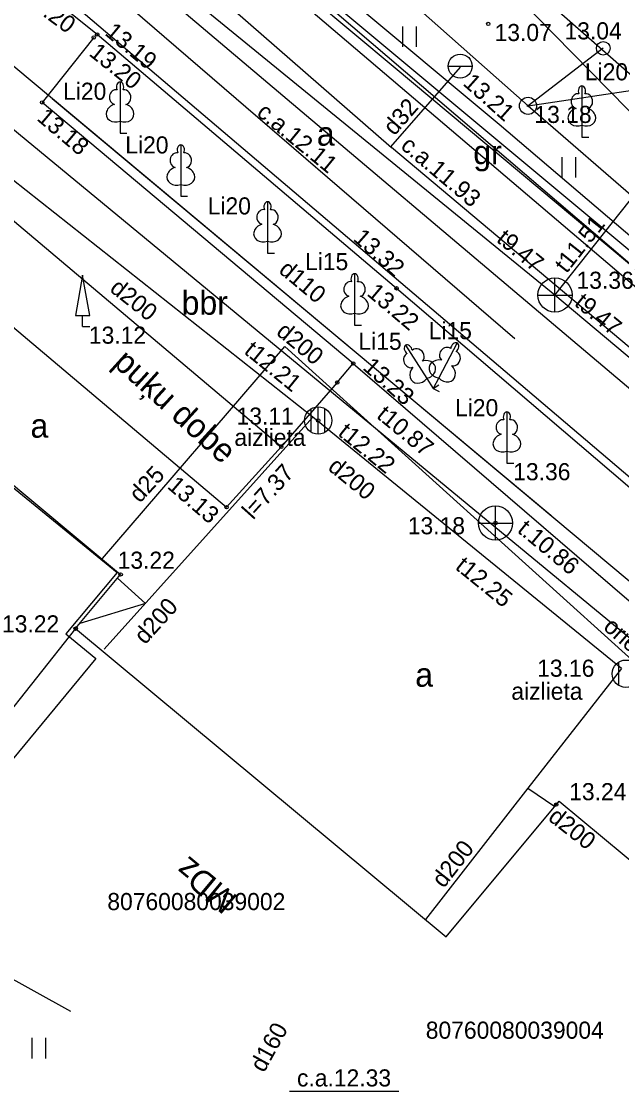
# Model space of a CAD drawing. Extents: x 503877 to 504025, y 304562 to 304725.
# Drawn here: x 503957.69 to 503975.24, y 304562.03 to 304593.32 of the extents above; entities that cross this region are included whole.
import ezdxf

# ---------------------------------------------------------------- set-up
doc = ezdxf.new("R2010")
doc.units = 0
for name, color, linetype in [('20', 7, 'Continuous'), ('25', 7, 'Continuous'), ('41', 7, 'Continuous'), ('42', 7, 'Continuous'), ('APGS_ACRL_####_####_#', 7, 'Continuous'), ('APGS_ACRL_####_TKST_#', 7, 'Continuous'), ('APGS_VADP_ZSPR_####_#', 7, 'Continuous'), ('BUVE_EKAS_####_####_#', 7, 'Continuous'), ('BUVE_EKAS_ADRS_TKST_#', 7, 'Continuous'), ('CELI_CAPM_####_####_#', 7, 'Continuous'), ('CELI_CMAL_####_####_#', 7, 'Continuous'), ('CELI_CSEG_####_TKST_#', 7, 'Continuous'), ('CELI_TAKA_####_####_#', 7, 'Continuous'), ('ELEK_ELEM_####_####_#', 7, 'Continuous'), ('ELEK_STUT_####_####_#', 7, 'Continuous'), ('ELEK_VADV_ZSPR_####_#', 7, 'Continuous'), ('GAZE_VADP_VSP2_####_#', 7, 'Continuous'), ('Level 46', 7, 'Continuous'), ('LKAN_ELEM_####_####_#', 7, 'Continuous'), ('LKAN_ELEM_PAST_TKST_#', 7, 'Continuous'), ('LKAN_VADP_PAST_####_#', 7, 'Continuous'), ('LKAN_VADP_PAST_TKST_#', 7, 'Continuous'), ('RELJ_AATZ_####_TKST_#', 7, 'Continuous'), ('RELJ_ELEM_####_####_#', 7, 'Continuous'), ('SAKK_KKAN_####_####_#', 7, 'Continuous'), ('SAKT_VADP_KABE_####_#', 7, 'Continuous'), ('SAKT_VADP_NEDR_####_#', 7, 'Continuous'), ('SKAN_DETP_PAST_####_#', 7, 'Continuous'), ('SKAN_ELEM_####_####_#', 7, 'Continuous'), ('SKAN_ELEM_PAST_TKST_#', 7, 'Continuous'), ('SKAN_VADP_PAST_####_#', 7, 'Continuous'), ('SKAN_VADP_PAST_####_I', 7, 'Continuous'), ('SKAN_VADP_PAST_TKST_#', 7, 'Continuous'), ('SKAN_VADP_PAST_TKST_I', 7, 'Continuous'), ('SKAN_VADP_SPDK_TKST_I', 7, 'Continuous'), ('TERT_DIAM_####_TKST_#', 7, 'Continuous'), ('TERT_ELEM_####_####_#', 7, 'Continuous'), ('TERT_IZMT_####_TKST_#', 7, 'Continuous'), ('UDTK_ELEM_####_####_#', 7, 'Continuous'), ('UDTK_ELEM_####_TKST_#', 7, 'Continuous'), ('UDTK_VADP_NEDR_####_#', 7, 'Continuous'), ('UDTK_VADP_NEDR_TKST_#', 7, 'Continuous'), ('UDTK_VADP_UDEN_####_I', 7, 'Continuous'), ('UDTK_VADP_UDEN_TKST_I', 7, 'Continuous')]:
    doc.layers.add(name, color=color, linetype=linetype)

msp = doc.modelspace()

# ---------------------------------------------------------------- linework, layer by layer
at = {"layer": '20'}
msp.add_line((503960.823, 304605.633), (503983.332, 304582.665), dxfattribs=at)
at = {"layer": '25'}
msp.add_line((503924.947, 304625.297), (503985.325, 304574.255), dxfattribs=at)
at = {"layer": '42'}
msp.add_lwpolyline([(503940.294, 304598.947), (503951.661, 304589.773), (503949.864, 304587.645), (503954.733, 304583.621), (503953.927, 304582.557), (503960.49, 304577.208), (503958.987, 304575.41), (503959.865, 304574.697), (503955.838, 304569.828), (503955.063, 304570.502), (503953.67, 304568.891), (503946.74, 304574.542), (503947.217, 304575.092), (503942.561, 304578.835), (503942.084, 304578.358), (503930.754, 304587.457), (503939.344, 304597.708)], close=True, dxfattribs=at)
at = {"layer": 'APGS_ACRL_####_####_#'}
msp.add_line((503958.587, 304591.069), (503973.167, 304578.886), dxfattribs=at)
at = {"layer": 'APGS_VADP_ZSPR_####_#'}
msp.add_line((503955.752, 304593.437), (503977.746, 304575.06), dxfattribs=at)
at = {"layer": 'BUVE_EKAS_####_####_#'}
for p, q in [((503954.167, 304582.49), (503960.588, 304577.15)), ((503959.271, 304575.566), (503960.588, 304577.15)), ((503959.271, 304575.566), (503955.082, 304570.298)), ((503959.271, 304575.566), (503970.108, 304566.552)), ((503970.108, 304566.552), (503973.411, 304570.524)), ((503973.411, 304570.524), (503979.555, 304565.414))]:
    msp.add_line(p, q, dxfattribs=at)
at = {"layer": 'CELI_CAPM_####_####_#'}
for p, q in [((503968.656, 304585.514), (503959.9, 304592.938)), ((503982.4, 304573.765), (503968.656, 304585.514))]:
    msp.add_line(p, q, dxfattribs=at)
at = {"layer": 'CELI_CMAL_####_####_#'}
for p, q in [((503982.055, 304580.09), (503962.594, 304596.657)), ((503959.9, 304592.938), (503957.88, 304594.554)), ((503959.802, 304592.849), (503958.292, 304590.951)), ((503967.389, 304583.318), (503958.292, 304590.951)), ((503965.285, 304580.881), (503956.281, 304588.468)), ((503954.789, 304586.616), (503963.685, 304579.115)), ((503966.922, 304582.761), (503967.389, 304583.318)), ((503967.389, 304583.318), (503981.868, 304570.859)), ((503966.922, 304582.761), (503965.285, 304580.881)), ((503963.685, 304579.115), (503965.285, 304580.881))]:
    msp.add_line(p, q, dxfattribs=at)
at = {"layer": 'CELI_TAKA_####_####_#'}
msp.add_line((503962.913, 304596.977), (503982.372, 304580.35), dxfattribs=at)
at = {"layer": 'ELEK_ELEM_####_####_#'}
for centre, radius in [((503974.701, 304592.532), 0.2), ((503972.501, 304590.85), 0.25), ((503972.501, 304590.85), 0.0225)]:
    msp.add_circle(centre, radius, dxfattribs=at)
at = {"layer": 'ELEK_STUT_####_####_#'}
msp.add_line((503974.701, 304592.532), (503972.501, 304590.85), dxfattribs=at)
at = {"layer": 'ELEK_VADV_ZSPR_####_#'}
for p, q in [((503938.2, 304621.309), (503972.501, 304590.85)), ((503972.501, 304590.85), (503977.734, 304591.644)), ((503972.501, 304590.85), (504000, 304566.991))]:
    msp.add_line(p, q, dxfattribs=at)
at = {"layer": 'GAZE_VADP_VSP2_####_#'}
for p, q in [((503958.172, 304594.706), (503971.829, 304583.093)), ((503971.829, 304583.093), (503992.301, 304565.684))]:
    msp.add_line(p, q, dxfattribs=at)
at = {"layer": 'Level 46'}
msp.add_line((503943.333, 304620.019), (504006.701, 304564.361), dxfattribs=at)
at = {"layer": 'LKAN_ELEM_####_####_#'}
for p, q in [((503966.363, 304581.251), (503966.363, 304582.051)), ((503966.163, 304581.305), (503966.163, 304581.997)), ((503966.563, 304581.305), (503966.563, 304581.997)), ((503975.16, 304573.902), (503975.16, 304574.594))]:
    msp.add_line(p, q, dxfattribs=at)
for centre in [(503966.363, 304581.651), (503975.36, 304574.248)]:
    msp.add_circle(centre, 0.4, dxfattribs=at)
at = {"layer": 'LKAN_VADP_PAST_####_#'}
for p, q in [((503966.208, 304581.751), (503953.386, 304591.874)), ((503966.208, 304581.751), (503960.104, 304574.963)), ((503975.237, 304574.404), (503966.208, 304581.751)), ((503961.31, 304576.305), (503960.495, 304577.038)), ((503961.31, 304576.305), (503959.391, 304575.711)), ((503975.237, 304574.404), (503972.499, 304570.901)), ((503972.499, 304570.901), (503969.498, 304567.06)), ((503972.499, 304570.901), (503973.281, 304570.367))]:
    msp.add_line(p, q, dxfattribs=at)
at = {"layer": 'RELJ_ELEM_####_####_#'}
for centre in [(503959.9, 304592.938), (503971.337, 304593.245), (503959.802, 304592.849), (503958.292, 304590.951), (503968.656, 304585.514), (503967.389, 304583.318), (503966.922, 304582.761), (503966.363, 304581.651), (503965.285, 304580.881), (503963.685, 304579.115), (503971.549, 304578.653), (503960.588, 304577.15), (503959.271, 304575.566), (503973.326, 304570.421)]:
    msp.add_circle(centre, 0.05, dxfattribs=at)
at = {"layer": 'SAKK_KKAN_####_####_#'}
for p, q in [((503968.613, 304591.954), (503945.607, 304611.208)), ((503986.057, 304577.347), (503968.613, 304591.954))]:
    msp.add_line(p, q, dxfattribs=at)
at = {"layer": 'SAKT_VADP_KABE_####_#'}
for p, q in [((503971.653, 304590.306), (503940.354, 304616.433)), ((503991.251, 304573.616), (503971.653, 304590.306)), ((503959.129, 304564.37), (503952.415, 304568.091))]:
    msp.add_line(p, q, dxfattribs=at)
at = {"layer": 'SAKT_VADP_NEDR_####_#'}
msp.add_line((503997.217, 304568.475), (503924.507, 304629.123), dxfattribs=at)
at = {"layer": 'SKAN_DETP_PAST_####_#'}
msp.add_line((503968.726, 304562.03), (503965.529, 304562.03), dxfattribs=at)
at = {"layer": 'SKAN_ELEM_####_####_#'}
for p, q in [((503973.287, 304584.819), (503973.287, 304585.819)), ((503972.787, 304585.319), (503973.787, 304585.319)), ((503971.549, 304578.153), (503971.549, 304579.153)), ((503971.049, 304578.653), (503972.049, 304578.653))]:
    msp.add_line(p, q, dxfattribs=at)
for centre in [(503973.287, 304585.319), (503971.549, 304578.653)]:
    msp.add_circle(centre, 0.5, dxfattribs=at)
at = {"layer": 'SKAN_VADP_PAST_####_#'}
for p, q in [((503971.339, 304578.696), (503938.881, 304605.476)), ((503984.286, 304568.011), (503971.339, 304578.696))]:
    msp.add_line(p, q, dxfattribs=at)
at = {"layer": 'SKAN_VADP_PAST_####_I'}
for p, q in [((503973.287, 304585.319), (503945.224, 304608.195)), ((503973.287, 304585.319), (503976.039, 304588.789)), ((503995.552, 304566.538), (503973.287, 304585.319))]:
    msp.add_line(p, q, dxfattribs=at)
at = {"layer": 'TERT_ELEM_####_####_#'}
for p, q in [((503968.842, 304592.574), (503968.842, 304593.174)), ((503969.242, 304592.574), (503969.242, 304593.174)), ((503960.571, 304590.398), (503960.571, 304590.051)), ((503974.076, 304590.281), (503974.076, 304589.934)), ((503960.571, 304590.051), (503960.771, 304590.051)), ((503974.076, 304589.934), (503974.276, 304589.934)), ((503973.499, 304588.751), (503973.499, 304589.351)), ((503973.899, 304588.751), (503973.899, 304589.351)), ((503962.347, 304588.553), (503962.347, 304588.206)), ((503962.347, 304588.206), (503962.547, 304588.206)), ((503964.883, 304586.893), (503964.883, 304586.546)), ((503964.883, 304586.546), (503965.083, 304586.546)), ((503959.473, 304584.396), (503959.473, 304584.716)), ((503967.428, 304584.788), (503967.428, 304584.441)), ((503959.473, 304584.396), (503959.683, 304584.396)), ((503967.428, 304584.441), (503967.628, 304584.441)), ((503969.541, 304582.881), (503969.729, 304582.589)), ((503969.89, 304582.896), (503969.729, 304582.589)), ((503969.729, 304582.589), (503969.897, 304582.697)), ((503969.729, 304582.589), (503969.906, 304582.496)), ((503971.882, 304580.751), (503971.882, 304580.404)), ((503971.882, 304580.404), (503972.082, 304580.404)), ((503958, 304563), (503958, 304563.6)), ((503958.4, 304563), (503958.4, 304563.6))]:
    msp.add_line(p, q, dxfattribs=at)
for points in [[(503960.571, 304591.551), (503960.571, 304590.398)], [(503974.076, 304591.434), (503974.076, 304590.281)], [(503960.661, 304591.319), (503960.66, 304591.32)], [(503974.166, 304591.202), (503974.165, 304591.203)], [(503962.347, 304589.706), (503962.347, 304588.553)], [(503962.437, 304589.474), (503962.436, 304589.475)], [(503964.883, 304588.046), (503964.883, 304586.893)], [(503964.973, 304587.814), (503964.972, 304587.815)], [(503967.428, 304585.941), (503967.428, 304584.788)], [(503967.518, 304585.709), (503967.517, 304585.71)], [(503970.427, 304583.917), (503969.89, 304582.896)], [(503968.917, 304583.85), (503969.541, 304582.881)], [(503969.118, 304583.703), (503969.117, 304583.704)], [(503970.398, 304583.669), (503970.397, 304583.671)], [(503971.882, 304581.904), (503971.882, 304580.751)], [(503971.972, 304581.672), (503971.971, 304581.673)]]:
    msp.add_lwpolyline(points, dxfattribs=at)
msp.add_lwpolyline([(503959.263, 304584.716), (503959.683, 304584.716), (503959.473, 304585.896)], close=True, dxfattribs=at)
for centre, major_axis, ratio, start_param, end_param in [((503960.571, 304591.401), (0, -0.15), 0.707107, 3.14537, 5.287485), ((503960.571, 304591.401), (0, -0.15), 0.707107, 0.995701, 3.137816), ((503974.076, 304591.284), (0, -0.15), 0.707107, 3.14537, 5.287485), ((503974.076, 304591.284), (0, -0.15), 0.707107, 0.995701, 3.137816), ((503960.443, 304591.106), (-0.039, -0.212), 0.861323, 3.141593, 6.283185), ((503960.699, 304591.106), (0.039, -0.212), 0.861323, 0, 3.141593), ((503973.948, 304590.989), (-0.039, -0.212), 0.861323, 3.141593, 6.283185), ((503974.204, 304590.989), (0.039, -0.212), 0.861323, 0, 3.141593), ((503960.481, 304590.644), (0.307, 0.095), 0.814445, 1.570796, 4.752015), ((503960.661, 304590.644), (-0.307, 0.095), 0.814445, 1.531171, 4.712389), ((503973.986, 304590.527), (0.307, 0.095), 0.814445, 1.570796, 4.752015), ((503974.166, 304590.527), (-0.307, 0.095), 0.814445, 1.531171, 4.712389), ((503962.347, 304589.556), (0, -0.15), 0.707107, 3.14537, 5.287485), ((503962.347, 304589.556), (0, -0.15), 0.707107, 0.995701, 3.137816), ((503962.219, 304589.261), (-0.039, -0.212), 0.861323, 3.141593, 6.283185), ((503962.475, 304589.261), (0.039, -0.212), 0.861323, 0, 3.141593), ((503962.257, 304588.799), (0.307, 0.095), 0.814445, 1.570796, 4.752015), ((503962.437, 304588.799), (-0.307, 0.095), 0.814445, 1.531171, 4.712389), ((503964.883, 304587.896), (0, -0.15), 0.707107, 3.14537, 5.287485), ((503964.883, 304587.896), (0, -0.15), 0.707107, 0.995701, 3.137816), ((503964.755, 304587.601), (-0.039, -0.212), 0.861323, 3.141593, 6.283185), ((503965.011, 304587.601), (0.039, -0.212), 0.861323, 0, 3.141593), ((503964.793, 304587.139), (0.307, 0.095), 0.814445, 1.570796, 4.752015), ((503964.973, 304587.139), (-0.307, 0.095), 0.814445, 1.531171, 4.712389), ((503967.428, 304585.791), (0, -0.15), 0.707107, 3.14537, 5.287485), ((503967.428, 304585.791), (0, -0.15), 0.707107, 0.995701, 3.137816), ((503967.3, 304585.496), (-0.039, -0.212), 0.861323, 3.141593, 6.283185), ((503967.556, 304585.496), (0.039, -0.212), 0.861323, 0, 3.141593), ((503967.338, 304585.034), (0.307, 0.095), 0.814445, 1.570796, 4.752015), ((503967.518, 304585.034), (-0.307, 0.095), 0.814445, 1.531171, 4.712389), ((503970.357, 304583.784), (-0.07, -0.133), 0.707107, 3.14537, 5.287485), ((503970.357, 304583.784), (-0.07, -0.133), 0.707107, 0.995701, 3.137816), ((503969.05, 304583.407), (0.082, -0.2), 0.861323, 3.141593, 6.283185), ((503968.999, 304583.724), (0.081, -0.126), 0.707107, 3.14537, 5.287485), ((503968.998, 304583.724), (0.081, -0.126), 0.707107, 0.995701, 3.137816), ((503969.266, 304583.546), (0.148, -0.158), 0.861323, 0, 3.141593), ((503970.106, 304583.583), (-0.133, -0.17), 0.861323, 3.141593, 6.283185), ((503970.333, 304583.463), (-0.065, -0.206), 0.861323, 0, 3.141593), ((503969.483, 304583.136), (-0.309, -0.086), 0.814445, 1.531171, 4.712389), ((503969.925, 304583.156), (0.316, -0.059), 0.814445, 1.570796, 4.752015), ((503969.333, 304583.039), (0.206, 0.246), 0.814445, 1.570796, 4.752015), ((503970.084, 304583.072), (-0.227, 0.227), 0.814445, 1.531171, 4.712389), ((503971.882, 304581.754), (0, -0.15), 0.707107, 3.14537, 5.287485), ((503971.882, 304581.754), (0, -0.15), 0.707107, 0.995701, 3.137816), ((503971.754, 304581.459), (-0.039, -0.212), 0.861323, 3.141593, 6.283185), ((503972.01, 304581.459), (0.039, -0.212), 0.861323, 0, 3.141593), ((503971.792, 304580.997), (0.307, 0.095), 0.814445, 1.570796, 4.752015), ((503971.972, 304580.997), (-0.307, 0.095), 0.814445, 1.531171, 4.712389)]:
    msp.add_ellipse(centre, major_axis=major_axis, ratio=ratio, start_param=start_param, end_param=end_param, dxfattribs=at)
at = {"layer": 'UDTK_ELEM_####_####_#'}
msp.add_line((503970.166, 304592.011), (503970.868, 304592.011), dxfattribs=at)
msp.add_circle((503970.517, 304592.011), 0.351, dxfattribs=at)
at = {"layer": 'UDTK_VADP_NEDR_####_#'}
for p, q in [((503972.119, 304584.039), (503959.145, 304595.208)), ((503960.057, 304577.619), (503965.385, 304583.819)), ((503965.385, 304583.819), (503982.325, 304568.514))]:
    msp.add_line(p, q, dxfattribs=at)
at = {"layer": 'UDTK_VADP_UDEN_####_I'}
for p, q in [((503942.658, 304612.162), (503968.511, 304589.634)), ((503968.492, 304589.65), (503970.526, 304591.984)), ((504000, 304563.139), (503968.511, 304589.634))]:
    msp.add_line(p, q, dxfattribs=at)

# ---------------------------------------------------------------- texts
at = {"layer": '41'}
for s, p in [('80760080039002', (503960.198, 304567.337)), ('80760080039004', (503969.51, 304563.576))]:
    msp.add_text(s, height=0.5, dxfattribs=at).set_placement(p)
at = {"layer": 'APGS_ACRL_####_TKST_#'}
msp.add_text('d110', height=0.5, rotation=320.118, dxfattribs=at).set_placement((503965.182, 304585.999))
at = {"layer": 'BUVE_EKAS_ADRS_TKST_#'}
msp.add_text('MDz', height=0.7, rotation=140.2493, dxfattribs=at).set_placement((503964.046, 304567.717))
at = {"layer": 'CELI_CSEG_####_TKST_#'}
for s, p in [('a', (503966.324, 304589.686)), ('gr', (503970.899, 304589.142)), ('bbr', (503962.371, 304584.743)), ('a', (503957.951, 304581.149)), ('a', (503969.202, 304573.868))]:
    msp.add_text(s, height=0.7, dxfattribs=at).set_placement(p)
at = {"layer": 'LKAN_ELEM_PAST_TKST_#'}
for s, p in [(' 13.11', (503963.791, 304581.53)), (' 13.16', (503972.582, 304574.159))]:
    msp.add_text(s, height=0.5, dxfattribs=at).set_placement(p)
at = {"layer": 'LKAN_VADP_PAST_TKST_#'}
for s, rotation, p in [('d200', 321.7088, (503960.238, 304585.45)), ('t12.21', 320.8644, (503964.167, 304583.632)), ('t12.22', 320.8644, (503966.913, 304581.24)), ('d200', 320.8644, (503966.618, 304580.232)), ('l=7.37', 48.0355, (503964.463, 304578.726)), ('t12.25', 320.8644, (503970.343, 304577.329)), ('d200', 48.0355, (503961.302, 304575.077)), ('d200', 321.9928, (503973.058, 304569.988)), ('d200', 51.9928, (503970.034, 304567.955))]:
    msp.add_text(s, height=0.5, rotation=rotation, dxfattribs=at).set_placement(p)
at = {"layer": 'RELJ_AATZ_####_TKST_#'}
for s, rotation, p in [(' 13.20', 323.7822, (503957.533, 304594.043)), (' 13.19', 320.3031, (503959.953, 304593.063)), (' 13.20', 321.3386, (503959.49, 304592.459)), (' 13.18', 319.8341, (503957.969, 304590.569)), (' 13.32', 318.4287, (503967.22, 304587.058)), (' 13.22', 319.8733, (503967.621, 304585.448)), (' 13.23', 318.6371, (503967.5, 304583.289)), (' 13.13', 319.3328, (503961.782, 304579.813))]:
    msp.add_text(s, height=0.5, rotation=rotation, dxfattribs=at).set_placement(p)
for s, p in [(' 13.04', (503973.382, 304592.793)), (' 13.07', (503971.337, 304592.745)), (' 13.18', (503972.501, 304590.35)), (' 13.12', (503959.473, 304583.896)), (' 13.36', (503971.882, 304579.904)), (' 13.22', (503960.314, 304577.317)), (' 13.22', (503956.932, 304575.455)), (' 13.24', (503973.519, 304570.549))]:
    msp.add_text(s, height=0.5, dxfattribs=at).set_placement(p)
at = {"layer": 'SKAN_ELEM_PAST_TKST_#'}
for s, p in [(' 13.36', (503973.733, 304585.501)), ('aizlieta', (503963.914, 304580.908)), (' 13.18', (503968.798, 304578.324)), ('aizlieta', (503972.013, 304573.486))]:
    msp.add_text(s, height=0.5, dxfattribs=at).set_placement(p)
at = {"layer": 'SKAN_VADP_PAST_TKST_#'}
for s, rotation, p in [('d200', 320.4757, (503965.108, 304584.188)), ('t10.87', 320.4757, (503968.041, 304581.75)), ('t.10.86', 320.4676, (503972.159, 304578.408)), ('d160', 61.2443, (503964.781, 304562.561))]:
    msp.add_text(s, height=0.5, rotation=rotation, dxfattribs=at).set_placement(p)
msp.add_text('c.a.12.33', height=0.5, dxfattribs=at).set_placement((503965.745, 304562.18))
at = {"layer": 'SKAN_VADP_PAST_TKST_I'}
for s, rotation, p in [('t11.51', 51.5826, (503973.626, 304585.929)), ('t9.47', 320.8143, (503971.547, 304586.901)), ('t9.47', 320.8143, (503973.825, 304585.036))]:
    msp.add_text(s, height=0.5, rotation=rotation, dxfattribs=at).set_placement(p)
at = {"layer": 'SKAN_VADP_SPDK_TKST_I'}
msp.add_text('c.a.12.11', height=0.5, rotation=320.6077, dxfattribs=at).set_placement((503964.535, 304590.595))
at = {"layer": 'TERT_DIAM_####_TKST_#'}
for s, p in [('Li20', (503974.163, 304591.595)), ('Li20', (503958.904, 304591.027)), ('Li20', (503960.723, 304589.458)), ('Li20', (503963.133, 304587.675)), ('Li15', (503965.979, 304586.047)), ('Li15', (503969.595, 304584.027)), ('Li15', (503967.542, 304583.718)), ('Li20', (503970.366, 304581.776))]:
    msp.add_text(s, height=0.5, dxfattribs=at).set_placement(p)
at = {"layer": 'TERT_IZMT_####_TKST_#'}
msp.add_text('puķu dobe', height=0.7, rotation=317.7627, dxfattribs=at).set_placement((503960.335, 304583.287))
at = {"layer": 'UDTK_ELEM_####_TKST_#'}
msp.add_text(' 13.21', height=0.5, rotation=318.3362, dxfattribs=at).set_placement((503970.433, 304591.599))
at = {"layer": 'UDTK_VADP_NEDR_TKST_#'}
for s, rotation, p in [('d25', 47.0193, (503961.148, 304579.217)), ('orient', 318.7792, (503974.672, 304575.569))]:
    msp.add_text(s, height=0.5, rotation=rotation, dxfattribs=at).set_placement(p)
at = {"layer": 'UDTK_VADP_UDEN_TKST_I'}
for s, rotation, p in [('d32', 48.9315, (503968.592, 304589.954)), ('c.a.11.93', 319.9227, (503968.745, 304589.628))]:
    msp.add_text(s, height=0.5, rotation=rotation, dxfattribs=at).set_placement(p)

doc.saveas('drawing.dxf')
